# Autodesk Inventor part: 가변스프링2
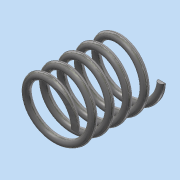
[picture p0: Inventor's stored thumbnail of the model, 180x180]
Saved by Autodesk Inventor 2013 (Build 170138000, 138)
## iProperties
Created: 2018-10
Part Number: 가변스프링2
Material: 스테인리스강
Document SubType Name: Modeling
Designer: Administrator
Density: 8.08 g/cm^3
Mass: 6.26686 g
Surface Area: 15.7589 cm^2
Volume: 0.775602 cm^3
Author: Administrator
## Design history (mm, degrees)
sketch "스케치1"
  geometry: L1 (0, 0)-(0, 29.23); L2 (0, 0)-(8, 0); L3 (0, 29.23)-(8, 29.23); C1 r 1 at (8, 0)
  constraints: 6 end point, 1 centre point, 1 coincident, 1 parallel, 1 perpendicular, 1 vertical
  dimensions: "d0" = 29.23004 distance of L1.start L1.end (derived); "d1" = 8 distance of L1.start L2.end; "d2" = 2 diameter of C1; "d3" = 8 distance of L1.end L3.end
feature "코일1" sketch "스케치1" pitch "d4" = 29.23004 (= d0); turns "d6" = 5; dims "d5" = 29.23004 (= d0), "d7" = 0, angle "d8" = 90 deg, angle "d9" = 90 deg, "d10" = 0, "d11" = 0
sketch "스케치2"
  geometry: L1 (29.23, 11)-(0, 11); L2 (0, 11)-(0, -11); L3 (0, -11)-(29.23, -11); L4 (29.23, -11)-(29.23, 11); 2 further points
  constraints: 8 end point, 2 parallel, 1 coincident, 1 horizontal, 1 midpoint, 1 perpendicular
  dimensions: "d12" = 29.23004 distance of L2.end L3.end (derived); "d16" = 22 distance of L3.end L1.start
extrude "돌출1" sketch "스케치2" stored distance "d14" = 0; taper "d15" = 0 deg
node "솔리드1"
